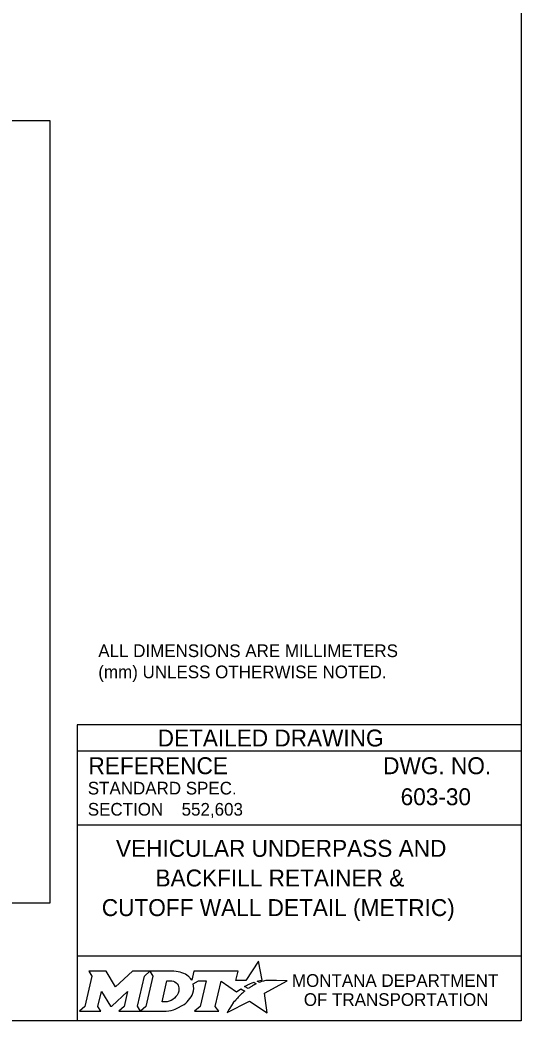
# Model space of a CAD drawing. Extents: x 49991.4 to 50021, y 49987.6 to 50011.4.
# Drawn here: x 50014.38 to 50016.75, y 49987.799 to 49992.53 of the extents above; entities that cross this region are included whole.
import ezdxf

# ---------------------------------------------------------------- set-up
doc = ezdxf.new("R2010")
doc.units = 0
for name, color, linetype in [('Default', 7, 'Continuous'), ('Level 1', 7, 'Continuous'), ('Level 2', 7, 'Continuous'), ('Level 5', 7, 'Continuous')]:
    doc.layers.add(name, color=color, linetype=linetype)

msp = doc.modelspace()

# ---------------------------------------------------------------- linework, layer by layer
at = {"layer": 'Default'}
for points in [[(50015.5126, 49987.9811), (50015.5023, 49987.9867), (50015.5139, 49987.9895), (50015.5255, 49987.9915), (50015.5081, 49988.0816), (50015.4486, 49987.9903), (50015.4013, 49987.9896), (50015.4116, 49988.0337), (50015.2024, 49988.0338), (50015.1923, 49987.9913), (50015.1865, 49987.9996)], [(50014.7056, 49988.0338), (50014.7197, 49988.0104), (50014.6862, 49987.8671), (50014.6605, 49987.8446), (50014.7621, 49987.8446), (50014.7486, 49987.8674), (50014.7648, 49987.9375), (50014.8085, 49987.8685), (50014.8138, 49987.8685), (50014.8889, 49987.938), (50014.8725, 49987.8669), (50014.8478, 49987.8449), (50014.9494, 49987.8449), (50014.9356, 49987.8682), (50014.9688, 49988.0106)], [(50014.9688, 49988.0106), (50014.9941, 49988.0338), (50014.9117, 49988.0338), (50014.8321, 49987.9608), (50014.7876, 49988.0335), (50014.7056, 49988.0338)], [(50015.1077, 49988.0338), (50014.9941, 49988.0338), (50015.0088, 49988.0109), (50014.9749, 49987.8671), (50014.9494, 49987.8449), (50015.06, 49987.8449)], [(50015.1317, 49987.9471), (50015.1305, 49987.939), (50015.1273, 49987.9297), (50015.1231, 49987.9215), (50015.1175, 49987.914), (50015.111, 49987.9071), (50015.1031, 49987.9008), (50015.0948, 49987.8961), (50015.0857, 49987.8922), (50015.0766, 49987.8899), (50015.0674, 49987.889), (50015.0515, 49987.889), (50015.0751, 49987.989), (50015.0911, 49987.989), (50015.0987, 49987.9884), (50015.1063, 49987.9865), (50015.1129, 49987.9835), (50015.119, 49987.9793), (50015.1238, 49987.9743), (50015.1275, 49987.9683), (50015.1302, 49987.9621), (50015.1318, 49987.9547), (50015.1318, 49987.9517), (50015.1317, 49987.9471)], [(50015.1991, 49987.9747), (50015.2237, 49987.9878), (50015.2606, 49987.9878), (50015.232, 49987.8673), (50015.2045, 49987.8446), (50015.3207, 49987.8446), (50015.3037, 49987.8675), (50015.3319, 49987.9877), (50015.4032, 49987.936), (50015.4243, 49987.9511), (50015.444, 49987.9402)], [(50015.3882, 49987.8843), (50015.3729, 49987.8599), (50015.3682, 49987.8524), (50015.3624, 49987.8438), (50015.3601, 49987.8395), (50015.4654, 49987.8926), (50015.5493, 49987.8375), (50015.5362, 49987.9302), (50015.6431, 49987.9886), (50015.5938, 49987.9894), (50015.5637, 49987.9898), (50015.5429, 49987.9901), (50015.5361, 49987.9886), (50015.5312, 49987.9874), (50015.5228, 49987.9851), (50015.5126, 49987.9811)], [(50015.4622, 49987.9535), (50015.4598, 49987.9518), (50015.4415, 49987.9614), (50015.4518, 49987.9671), (50015.4559, 49987.9693), (50015.4645, 49987.9733), (50015.4702, 49987.9759), (50015.4781, 49987.9789), (50015.4854, 49987.9816), (50015.4972, 49987.9742), (50015.4932, 49987.9721), (50015.4886, 49987.9696), (50015.4844, 49987.9674), (50015.4794, 49987.9645), (50015.4775, 49987.9634), (50015.4748, 49987.9618), (50015.4723, 49987.9604), (50015.47, 49987.9588), (50015.4674, 49987.957), (50015.4647, 49987.9552), (50015.4622, 49987.9535)], [(50015.4021, 49987.9004), (50015.4021, 49987.9004)], [(50015.1057, 49987.8522), (50015.1141, 49987.8548), (50015.1271, 49987.8602), (50015.1475, 49987.8712)]]:
    msp.add_lwpolyline(points, dxfattribs=at)
for centre, radius, start, end in [((50015.0868, 49987.9727), 0.1183, 300.9103, 339.1383), ((50015.1308, 49987.9554), 0.0709, 339.5329, 15.8582)]:
    msp.add_arc(centre, radius, start, end, dxfattribs=at)
for centre, major_axis, ratio, start_param, end_param in [((50015.1056, 49987.9864), (0.0834, -0.0037), 0.568097, 0.61298, 1.570796), ((50015.1612, 49987.9937), (0.0361, -0.0295), 0.469099, 1.225588, 1.570796), ((50015.4329, 49987.9305), (-0.0112, -0.0097), 0.021651, 3.157348, 6.283185), ((50015.3952, 49987.8923), (-0.00694, -0.00806), 0.008222, 0, 3.137361), ((50015.4119, 49987.9106), (-0.0098, -0.0102), 0.016458, 3.141593, 6.279097), ((50015.0603, 49987.9932), (0, 0.1484), 0.987302, 3.139398, 3.456847)]:
    msp.add_ellipse(centre, major_axis=major_axis, ratio=ratio, start_param=start_param, end_param=end_param, dxfattribs=at)
at = {"layer": 'Level 1'}
for points in [[(49999.3835, 49998.9992), (50016.7501, 49998.9992), (50016.7501, 49987.7988), (49999.3835, 49987.7988)], [(49999.5613, 49992.0549), (50014.5211, 49992.0549), (50014.5211, 49988.3552), (49999.5613, 49988.3552)]]:
    msp.add_lwpolyline(points, close=True, dxfattribs=at)
at = {"layer": 'Level 5'}
for p, q in [((50016.7501, 49989.1988), (50014.6501, 49989.1988)), ((50014.6501, 49989.1988), (50014.6501, 49987.7988)), ((50016.7501, 49989.0738), (50014.6501, 49989.0738)), ((50016.7501, 49988.7238), (50014.6501, 49988.7238)), ((50016.7501, 49988.1057), (50014.6501, 49988.1057))]:
    msp.add_line(p, q, dxfattribs=at)

# ---------------------------------------------------------------- texts
at = {"layer": 'Default'}
for s, p in [('MONTANA DEPARTMENT', (50015.6663, 49987.96)), ('OF TRANSPORTATION', (50015.7225, 49987.87))]:
    msp.add_text(s, height=0.06, dxfattribs=at).set_placement(p)
at = {"layer": 'Level 2'}
for s, height, p in [('ALL DIMENSIONS ARE MILLIMETERS', 0.06, (50014.7501, 49989.5188)), ('(mm) UNLESS OTHERWISE NOTED.', 0.06, (50014.7501, 49989.4188)), ('603-30', 0.08, (50016.1806, 49988.8187)), ('552,603', 0.06, (50015.1444, 49988.7693)), ('VEHICULAR UNDERPASS AND', 0.08, (50014.8336, 49988.5747)), ('BACKFILL RETAINER &', 0.08, (50015.0208, 49988.4347)), ('CUTOFF WALL DETAIL (METRIC)', 0.08, (50014.7666, 49988.2947))]:
    msp.add_text(s, height=height, dxfattribs=at).set_placement(p)
at = {"layer": 'Level 5'}
for s, height, p in [('DETAILED DRAWING', 0.0799, (50015.0311, 49989.0963)), ('REFERENCE', 0.08, (50014.7037, 49988.9654)), ('DWG. NO.', 0.08, (50016.0979, 49988.9654)), ('STANDARD SPEC.', 0.06, (50014.7004, 49988.8694)), ('SECTION', 0.06, (50014.7004, 49988.7694))]:
    msp.add_text(s, height=height, dxfattribs=at).set_placement(p)

doc.saveas('drawing.dxf')
